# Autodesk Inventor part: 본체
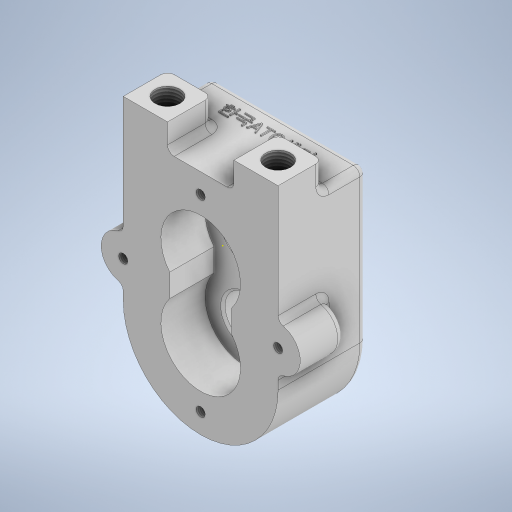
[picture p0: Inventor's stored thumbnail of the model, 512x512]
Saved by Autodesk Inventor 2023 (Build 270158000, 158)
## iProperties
Created: 2024-03
Part Number: 본체
Material: 일반
Document SubType Name: Modeling
Designer: asung
Density: 1 g/cm^3
Appearance: 기본값
Author: asung
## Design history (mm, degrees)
sketch "스케치1"
  geometry: L1 (-35, -34)-(35, -34); L2 (35, -34)-(35, 34); L3 (35, 34)-(-35, 34); L4 (-35, 34)-(-35, -34); L5 (-35, -34)-(35, 34); L6 (35, -34)-(-35, 34); C1 r 35 at (0, -34); 3 further points
  constraints: 12 end point, 3 midpoint, 2 parallel, 1 centre point, 1 horizontal, 1 perpendicular
  dimensions: "d0" = 70 distance of L3.end L2.end; "d1" = 68 distance of L2.end L1.end; "d2" = 70 diameter of C1
extrude "돌출1" new body sketch "스케치1" distance "d3" = 40; taper "d4" = 0 deg
sketch "스케치2"
  geometry: L1 (-35, 34)-(-35, -34) reference; L2 (35, -34)-(35, 34) reference; L3 (35, 34)-(-35, 34) reference; L4 (-35, 46)-(-15, 46); L5 (-15, 46)-(-15, 34); L6 (-15, 34)-(-35, 34); L7 (-35, 34)-(-35, 46); L8 (35, 34)-(15, 34); L9 (15, 34)-(15, 46); L10 (15, 46)-(35, 46); L11 (35, 46)-(35, 34); A1 r 35 centre (0, -34) between (-35, -34) and (35, -34) reference; 3 further points
  constraints: 16 end point, 4 parallel, 2 horizontal, 2 perpendicular
  dimensions: "d5" = 20 distance of L1.start L5.end; "d6" = 12 distance of L4.end L5.end; "d9" = 20 distance of L9.end L10.end; "d10" = 12 distance of L8.end L9.end
extrude "돌출2" join sketch "스케치2" distance "d11" = 20; taper "d12" = 0 deg
sketch "스케치3"
  geometry: L1 (-35, 46)-(-35, -34) reference; L2 (35, -34)-(35, 46) reference; L3 (35, 46)-(15, 46) reference; L4 (15, 46)-(15, 34) reference; L5 (15, 34)-(-15, 34) reference; L6 (-15, 34)-(-15, 46) reference; L7 (-15, 46)-(-35, 46) reference; L8 (-35, 46)-(-35, -17.5); L9 (35, 46)-(35, -17.5); C1 r 10 at (-35, -17.5); C2 r 10 at (35, -17.5); A1 r 35 centre (0, -34) between (-35, -34) and (35, -34) reference; 5 further points
  constraints: 4 end point, 2 centre point, 2 coincident, 2 point on line
  dimensions: "d13" = 63.5 distance of L1.start L8.end; "d14" = 10 radius of C1; "d15" = 63.5 distance of L2.end L9.end; "d16" = 10 radius of C2
extrude "돌출3" join sketch "스케치3" distance "d17" = 20; taper "d18" = 0 deg
fillet "모깎기1" dims "d19" = 3
fillet "모깎기2" dims "d20" = 3
sketch "스케치4"
  geometry: L1 (-35, 46)-(-35, -4.851) reference; L2 (-35, -30.149)-(-35, -34) reference; L3 (35, -34)-(35, -30.149) reference; L4 (35, -4.851)-(35, 46) reference; L5 (35, 46)-(15, 46) reference; L6 (15, 46)-(15, 34) reference; L7 (15, 34)-(-15, 34) reference; L8 (-15, 34)-(-15, 46) reference; L9 (-15, 46)-(-35, 46) reference; L10 (0, 34)-(0, -1); L11 (-14, -7.5)-(14, -7.5); L12 (14, -7.5)-(14, -27.5); L13 (14, -27.5)-(-14, -27.5); L14 (-14, -27.5)-(-14, -7.5); C1 r 18 at (0, -34); C2 r 18 at (0, -1); A1 r 3 centre (-38, -4.851) between (-37.308, -7.77) and (-35, -4.851) reference; A2 r 10 centre (-35, -17.5) between (-37.308, -7.77) and (-37.308, -27.23) reference; A3 r 3 centre (-38, -30.149) between (-35, -30.149) and (-37.308, -27.23) reference; A4 r 35 centre (0, -34) between (-35, -34) and (35, -34) reference; A5 r 3 centre (38, -30.149) between (37.308, -27.23) and (35, -30.149) reference; A6 r 10 centre (35, -17.5) between (37.308, -27.23) and (37.308, -7.77) reference; A7 r 3 centre (38, -4.851) between (35, -4.851) and (37.308, -7.77) reference; 7 further points
  constraints: 10 end point, 3 midpoint, 2 centre point, 2 coincident, 2 parallel, 1 horizontal, 1 horizontal alignment, 1 perpendicular, 1 vertical, 1 vertical alignment
  dimensions: "d22" = 36 diameter of C1; "d23" = 35 distance of L10.start L10.end; "d24" = 36 diameter of C2; "d25" = 28 distance of L12.end L13.end; "d26" = 20 distance of L11.end L12.end
extrude "돌출4" cut sketch "스케치4" distance "d27" = 20; taper "d28" = 0 deg
sketch "스케치7"
  geometry: 1 further point
sketch "스케치8"
  geometry: A1 r 18 centre (0, -34) between (-14, -22.686) and (14, -22.686) reference; 2 further points
  constraints: 1 coincident
hole "구멍2" sketch "스케치8" at (0, -34) diameter "d41" = 20; stored, may be unused: countersink angle "d45" = 90 deg, drill point angle "d47" = 0 deg; dims "d42" = 6, "d43" = 4, "d44" = 2, "d46" = 10
sketch "스케치9"
  geometry: L1 (34, 40)-(34, 0) reference; L2 (34, 0)-(-69, 0) reference; L3 (-24, 20)-(17, 20) reference; L4 (17, 20)-(17, 40) reference; L5 (17, 40)-(34, 40) reference; L6 (-69, 0)-(-69, 40) reference; L7 (-69, 40)-(-52, 40) reference; L8 (-52, 40)-(-52, 20) reference; L9 (-52, 20)-(-44, 20) reference; L10 (-44, 20)-(-44, 10) reference; L11 (-44, 10)-(-24, 10) reference; L12 (-24, 10)-(-24, 20) reference; L13 (34, 40)-(34, 0) reference; L14 (34, 0)-(-69, 0) reference; L15 (-24, 20)-(17, 20) reference; L16 (17, 20)-(17, 40) reference; L17 (17, 40)-(34, 40) reference; L18 (-69, 0)-(-69, 40) reference; L19 (-69, 40)-(-52, 40) reference; L20 (-52, 40)-(-52, 20) reference; L21 (-52, 20)-(-44, 20) reference; L22 (-44, 20)-(-44, 10) reference; L23 (-44, 10)-(-24, 10) reference; L24 (-24, 10)-(-24, 20) reference; L25 (-44, 20)-(-24, 20) reference; L26 (-24, 10)-(-44, 10) reference; L27 (-34, 20)-(-34, 5.959); L28 (-27, 10)-(-34, 5.959); L29 (-34, 5.959)-(-41, 10); 3 further points
  constraints: 6 end point, 2 point on line, 1 midpoint
  dimensions: "d49" = 14 diameter of L28.start L27; "d50" = 14 diameter of L29.end L27; "d51" = 120 deg angle of L29 L28; "d52" = 7 distance from line of L28.start L29
revolve "회전2" sketch "스케치9" stored, may be unused: angle "d53" = 90 deg
sketch "스케치10"
  geometry: 1 further point
sketch "스케치11"
  geometry: L1 (-14, -22.686)-(-14, -12.314) reference; L2 (14, -12.314)-(14, -22.686) reference; L3 (0, -1)-(0, 25); L4 (0, -34)-(0, -60); C1 r 10 at (0, -34) reference; A1 r 18 centre (0, -34) between (-14, -22.686) and (14, -22.686) reference; A2 r 18 centre (0, -1) between (14, -12.314) and (-14, -12.314) reference; 3 further points
  constraints: 4 end point, 2 coincident, 2 vertical
  dimensions: "d54" = 26 distance of L3.start L3.end; "d55" = 26 distance of L4.start L4.end
hole "구멍3" sketch "스케치11" at (0, 25), (0, -60) diameter "d56" = 4.134; stored, may be unused: countersink angle "d60" = 90 deg, drill point angle "d62" = 118 deg; dims "d57" = 10, "d58" = 4, "d59" = 2, "d61" = 12
sketch "스케치12"
  geometry: 1 further point
sketch "스케치13"
  geometry: 1 further point
sketch "스케치14"
  geometry: 1 further point
sketch "스케치15"
  geometry: L1 (35, 34)-(35, -34) reference; L2 (-35, 34)-(35, 34) reference; L3 (-35, -34)-(-35, 34) reference; L4 (0, 34)-(0, -1); C1 r 26 at (0, -1); C2 r 16 at (0, -1); A1 r 35 centre (0, -34) between (-35, -34) and (35, -34) reference; 1 further point
  constraints: 2 centre point, 2 coincident, 2 end point, 1 midpoint, 1 vertical
  dimensions: "d63" = 35 distance of L4.start L4.end; "d64" = 52 diameter of C1; "d65" = 32 diameter of C2
  node "투영된 루프9"
extrude "돌출5" join sketch "스케치15" distance "d66" = 6; taper "d67" = 0 deg
extrude "돌출6" join sketch "스케치15" distance "d68" = 10; taper "d69" = 0 deg
sketch "스케치16"
  geometry: 1 further point
fillet "모깎기3" dims "d70" = 3
sketch "스케치17"
  geometry: A1 r 18 centre (0, -1) between (14, -12.314) and (-14, -12.314) reference; 2 further points
  constraints: 1 coincident
hole "구멍4" sketch "스케치17" at (0, -1) diameter "d71" = 15; stored, may be unused: countersink angle "d75" = 90 deg, drill point angle "d77" = 0 deg; dims "d72" = 10, "d73" = 20, "d74" = 10, "d76" = 50
chamfer "모따기1" distance "d78" = 1; stored, may be unused: second distance "d79" = 2, angle "d80" = 45 deg
sketch "스케치18"
  geometry: L1 (25, 26.758)-(27.067, 28) reference; L2 (27.067, 28)-(27.067, 40) reference; L3 (27.067, 40)-(34, 40) reference; L4 (34, 40)-(34, 0) reference; L5 (34, 0)-(28, 0) reference; L6 (25, -3)-(25, -6) reference; L7 (25, -6)-(15, -6) reference; L8 (15, -6)-(15, -10) reference; L9 (15, -10)-(6.5, -10) reference; L10 (6.5, -10)-(6.5, 10) reference; L11 (6.5, 10)-(9, 10) reference; L12 (9, 10)-(9, 19) reference; L13 (9, 19)-(10, 20) reference; L14 (10, 20)-(17, 20) reference; L15 (17, 20)-(17, 40) reference; L16 (17, 40)-(22.933, 40) reference; L17 (22.933, 40)-(22.933, 28) reference; L18 (22.933, 28)-(25, 26.758) reference; L19 (-34, 5.959)-(-27, 10) reference; L20 (-27, 10)-(-24, 10) reference; L21 (-24, 10)-(-24, 20) reference; L22 (-24, 20)-(-12, 20) reference; L23 (-12, 20)-(-11, 19) reference; L24 (-11, 19)-(-11, 10) reference; L25 (-11, 10)-(-8.5, 10) reference; L26 (-8.5, 10)-(-8.5, -10) reference; L27 (-8.5, -10)-(-17, -10) reference; L28 (-17, -10)-(-17, -6) reference; L29 (-17, -6)-(-27, -6) reference; L30 (-27, -6)-(-27, -3) reference; L31 (-30, 0)-(-69, 0) reference; L32 (-69, 0)-(-69, 40) reference; L33 (-69, 40)-(-62.067, 40) reference; L34 (-62.067, 40)-(-62.067, 28) reference; L35 (-62.067, 28)-(-60, 26.758) reference; L36 (-60, 26.758)-(-57.933, 28) reference; L37 (-57.933, 28)-(-57.933, 40) reference; L38 (-57.933, 40)-(-52, 40) reference; L39 (-52, 40)-(-52, 20) reference; L40 (-52, 20)-(-44, 20) reference; L41 (-44, 20)-(-44, 10) reference; L42 (-44, 10)-(-41, 10) reference; L43 (-41, 10)-(-34, 5.959) reference; L44 (6.5, -10)-(-8.5, -10) reference; L45 (6.5, 10)-(-8.5, 10) reference; L46 (9, 10)-(-11, 10) reference; L47 (-11, 19)-(9, 19) reference; L48 (-1, -10)-(-1, 10); L49 (11.904, -10)-(11.5, -9.3); L50 (11.5, -9.3)-(11.5, -2.7); L51 (11.5, -2.7)-(-1, -2.7); A1 r 3 centre (28, -3) between (28, 0) and (25, -3) reference; A2 r 3 centre (-30, -3) between (-27, -3) and (-30, 0) reference; 2 further points
  constraints: 8 end point, 2 midpoint, 2 point on line, 1 perpendicular, 1 vertical
  dimensions: "d81" = 0.7 vertical distance of L49.start L49.end; "d82" = 7.3 vertical distance of L49.start L50.end; "d83" = 30 deg angle of L50 L49; "d84" = 25 diameter of L50 L48
revolve "회전3" sketch "스케치18" stored, may be unused: angle "d85" = 90 deg
chamfer "모따기2" distance "d86" = 1; stored, may be unused: second distance "d87" = 2, angle "d88" = 45 deg
sketch "스케치19"
  geometry: 1 further point
sketch "스케치20" dims "d89" = 42
  geometry: C1 r 26 at (0, 0) reference; C2 r 16 at (0, 0) reference; 3 further points
  constraints: 1 coincident, 1 vertical alignment, 2 other
hole "구멍5" sketch "스케치20" at (0, 21) diameter "d90" = 3.242; stored, may be unused: countersink angle "d94" = 90 deg, drill point angle "d96" = 118 deg; dims "d91" = 8, "d92" = 20, "d93" = 10, "d95" = 10
node "작업 평면1"
sketch "스케치23"
  geometry: L1 (20, 0)-(0, 0) reference; L2 (20, 0)-(20, 20) reference; L3 (0, 20)-(20, 20) reference; L4 (0, 0)-(0, 20) reference; L5 (70, 0)-(50, 0) reference; L6 (70, 0)-(70, 20) reference; L7 (50, 20)-(70, 20) reference; L8 (50, 0)-(50, 20) reference; 3 further points
  node "투영된 루프16"
  node "투영된 루프17"
sketch "스케치24"
  geometry: A1 r 10 centre (35, -17.5) between (37.308, -27.23) and (37.308, -7.77) reference; A2 r 10 centre (-35, -17.5) between (-37.308, -7.77) and (-37.308, -27.23) reference; 3 further points
  constraints: 2 coincident
hole "구멍7" sketch "스케치24" at (35, -17.5), (-35, -17.5) diameter "d109" = 4.134; stored, may be unused: countersink angle "d113" = 90 deg, drill point angle "d115" = 118 deg; dims "d110" = 10, "d111" = 4, "d112" = 2, "d114" = 12
sketch "스케치25"
  geometry: L1 (50, -40)-(20, -40) reference; L2 (70, 0)-(0, 0) reference; 3 further points
  constraints: 1 midpoint, 1 vertical alignment, 1 other
  dimensions: "d116" = 30 distance from line of L1 point (35, -10)
feature "엠보싱1" sketch "스케치25" dims "d117" = 0.5, "d118" = 0
hole "구멍8" sketch "스케치23" diameter "d119" = 10.5; stored, may be unused: countersink angle "d125" = 90 deg, drill point angle "d127" = 118 deg; dims "d120" = 11, "d121" = 0.62479, "d122" = 10.589, "d123" = 4, "d124" = 2, "d126" = 16
node "작업 평면2"
sketch "스케치27"
  geometry: 1 further point
node "작업 평면3"
fillet "모깎기4" dims "d137" = 3
chamfer "모따기3" distance "d138" = 1; stored, may be unused: second distance "d139" = 2, angle "d140" = 45 deg
fillet "모깎기5" dims "d141" = 3
fillet "모깎기6" dims "d142" = 3
node "솔리드1"
pattern_circular "원형 패턴1" dims angle "d98" = 360 deg
node "투영된 루프1"
node "투영된 루프2"
node "투영된 루프3"
node "투영된 루프7"
node "투영된 루프8"
node "투영된 루프10"
node "투영된 루프11"
node "투영된 루프12"
node "절단 모서리 투영2"
node "절단 모서리 투영3"
node "절단 모서리 투영4"
feature "A9D066F2-1C7D-4E18-AEED-F7BC21143FA4" dims "d41" = 20, "d42" = 6, "d43" = 4, "d44" = 2, "d45" = 90 deg, "d46" = 10, "d47" = 0
